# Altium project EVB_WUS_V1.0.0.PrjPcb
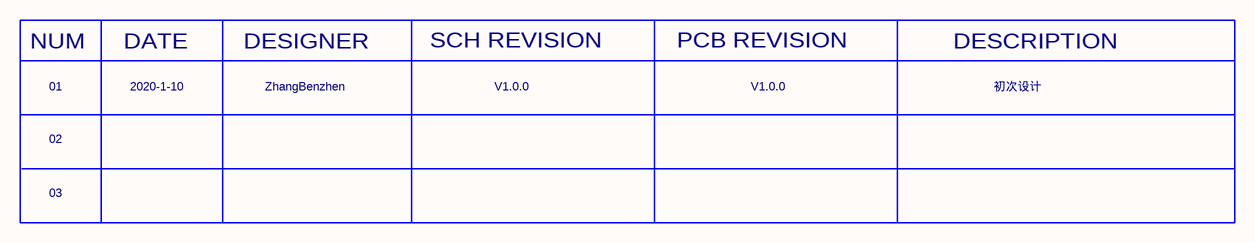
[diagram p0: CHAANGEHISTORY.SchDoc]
2 sheets, 10 parts. Net scope: global (net labels, ports and power ports of the same name join across sheets).
Sheets:
  CHAANGEHISTORY.SchDoc
  ATBM6032I.SchDoc

## Sheet CHAANGEHISTORY.SchDoc: EVB_WUS_V1.0.0
size A4; Revision: V1.0.0; SheetNumber: 1; SheetTotal: 2; Release Date: 2014-05-28; SchModifyDate: 2020.1.10; PCBVersion: V1.0.0; PCBPartNumber: EVB_WUS_V1.0.0

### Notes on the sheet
- SCH REVISION
- PCB REVISION
- NUM
- 01
- DATE
- 2020-1-10
- DESIGNER
- ZhangBenzhen
- V1.0.0
- DESCRIPTION
- 初次设计
- 02
- 03

## Sheet ATBM6032I.SchDoc: EVB_WUS_V1.0.0
size A4; Revision: V1.0.0; SheetNumber: 2; SheetTotal: 2
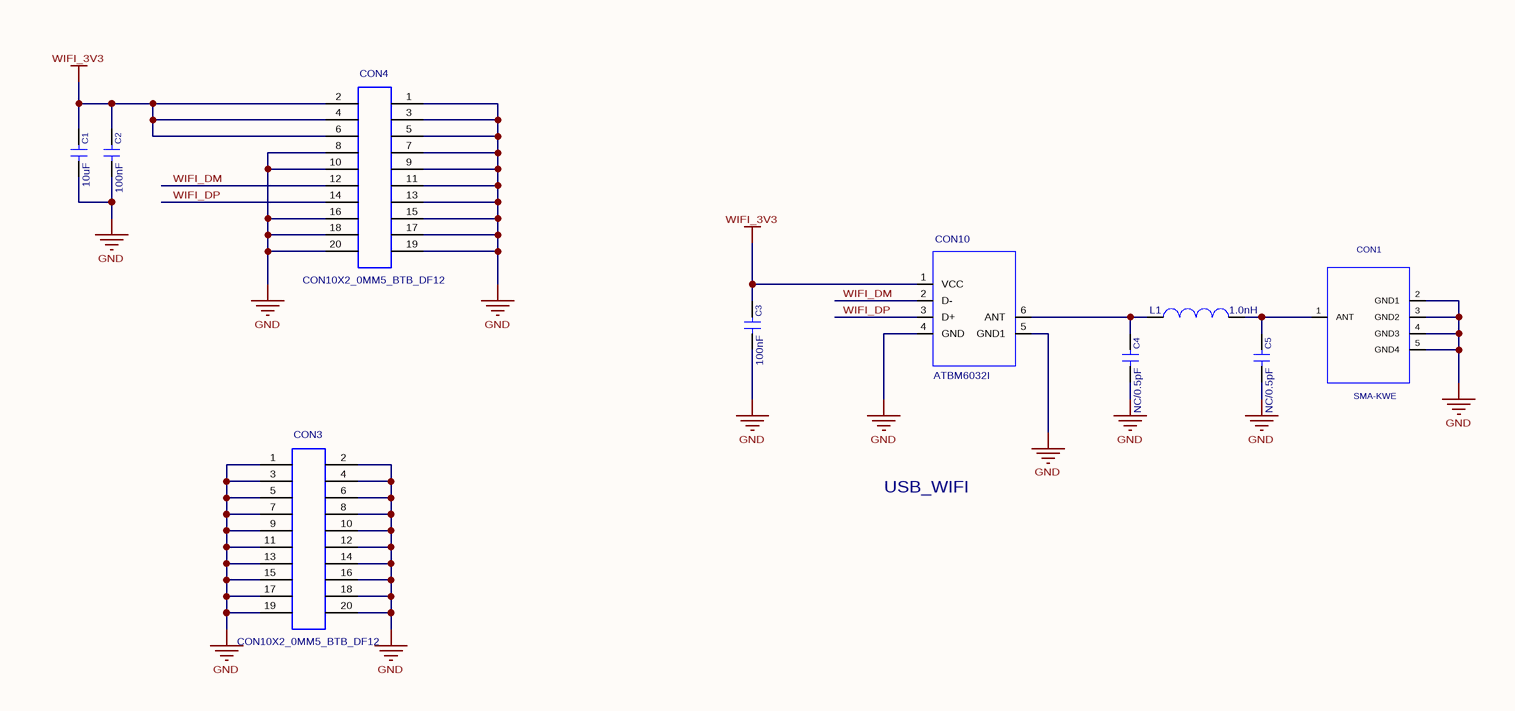
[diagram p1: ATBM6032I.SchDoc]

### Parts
C1  10uF  [C0603]
C2  100nF  [C0603]
C3  100nF  [C0603]
C4  NC/0.5pF  [C0402]
C5  NC/0.5pF  [C0402]
CON1  SMA-KWE  [SMA-KHD-92105001]
CON3  CON10X2_0MM5_BTB_DF12  [CON10X2_0MM5_BTB_DF12_N]
CON4  CON10X2_0MM5_BTB_DF12  [CON10X2_0MM5_BTB_DF12_N]
CON10  ATBM6032I  [USB_MODULE]
L1  1.0nH  [L0402]

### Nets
GND: C1.2 C2.2 C3.2 C4.2 C5.2 CON1.2(GND1) CON1.3(GND2) CON1.4(GND3) CON1.5(GND4) CON3.1 CON3.2 CON3.3 CON3.4 CON3.5 CON3.6 CON3.7 CON3.8 CON3.9 CON3.10 CON3.11 CON3.12 CON3.13 CON3.14 CON3.15 CON3.16 CON3.17 CON3.18 CON3.19 CON3.20 CON4.1 CON4.3 CON4.5 CON4.7 CON4.8 CON4.9 CON4.10 CON4.11 CON4.13 CON4.15 CON4.16 CON4.17 CON4.18 CON4.19 CON4.20 CON10.4(GND) CON10.5(GND1)
WIFI_3V3: C1.1 C2.1 C3.1 CON4.2 CON4.4 CON4.6 CON10.1(VCC)
WIFI_DM: CON4.12 CON10.2(D-)
WIFI_DP: CON4.14 CON10.3(D+)
NetC4_1: C4.1 CON10.6(ANT) L1.1
NetC5_1: C5.1 CON1.1(ANT) L1.2

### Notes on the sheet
- USB_WIFI

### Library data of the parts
C1 = CC0301064XX: C/C,10uF,6.3V,+/-20%,0603; Catalog: 陶瓷电容
C2 C3 = CC0301040XX: C/C,100nF,25V,+/-5%,0603; Catalog: 陶瓷电容
C4 C5 = CC0200R52XX: C/C,0.5pF,50V,±0.05pF ,0402,Murata; Remark: NC; Catalog: 陶瓷电容
CON1 = CNRFM0515XX: SMA-KWE,5pin,Normal，弯头正脚内孔，6*6*13&14.5；; Part Number_AK: CNRFM0501XX; Source_Path: I:\PROJECTFILES\CADENCE\AD11\AD11_AK9806_V2.1_20120202.DSN; Catalog: Connector
CON3 CON4 = CNBBM2000XX: 0.5mm ，BTB2*10Pin，SMT，公座，H3.0，DF12#(3.0)-20DS-0.5; PCB DECAL: CON10X2_0MM5_BTB_DF12_BOTTOM; Catalog: Connector
CON10 = MDWIFI052XX: USB2.0 WIFI Module,ATBM6032I,13 *12.2*1.8mm, IPEX,8pin; Part Number_AK: MDWIFI006XX; PCB DECAL: RL-UM02BS; Catalog: 集成电路
L1 = CL0201R00XX: C/L,1.0nH,0402,LQG15HS1N0S02D; Catalog: 贴片电感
